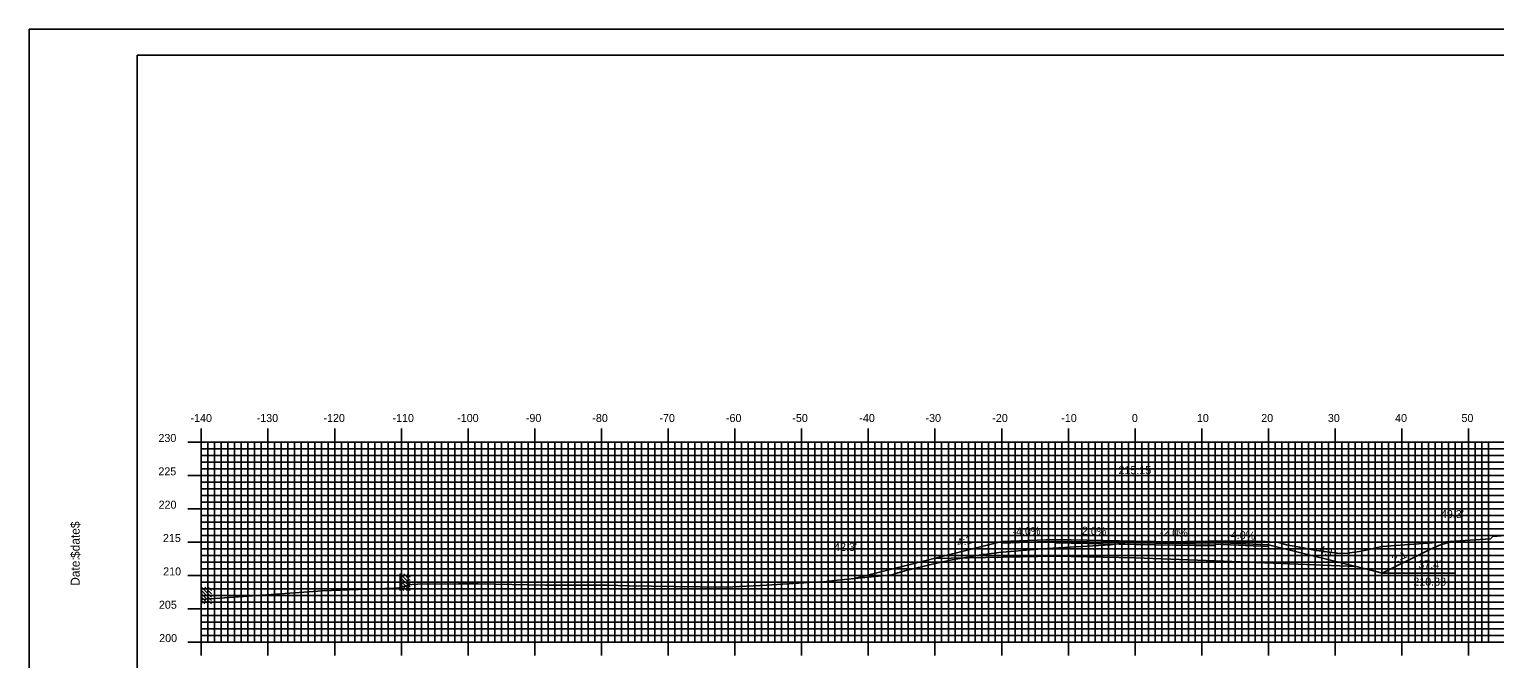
# Model space of a CAD drawing. Extents: x 851742 to 852085, y 364785 to 365005.
# Drawn here: x 851741.9 to 851961.6, y 364910.7 to 365005.1 of the extents above; entities that cross this region are included whole.
import ezdxf

# ---------------------------------------------------------------- set-up
doc = ezdxf.new("R2010")
doc.units = 0
for name, color, linetype in [('ANNOTATION', 7, 'Continuous'), ('BORDER', 7, 'Continuous'), ('D_Roadway_Centerline', 7, 'Continuous'), ('D_Roadway_Centerline_Text', 7, 'Continuous'), ('D_Roadway_Edge_Shoulder', 7, 'Continuous'), ('D_Roadway_Edge_TW', 7, 'Continuous'), ('D_Roadway_Pavement', 7, 'Continuous'), ('D_Roadway_SlopeLines', 7, 'Continuous'), ('D_Roadway_SubGrade', 7, 'Continuous'), ('D_Text_Standard', 7, 'Continuous'), ('H_V ANNOTATION', 7, 'Continuous'), ('M_Buildings_Rooftop', 7, 'Continuous'), ('MAJOR', 7, 'Continuous'), ('MINOR', 7, 'Continuous'), ('PDRAIN', 7, 'Continuous'), ('PLOT BOUNDARY', 7, 'Continuous'), ('S_Roadway_Centerline', 7, 'Continuous')]:
    doc.layers.add(name, color=color, linetype=linetype)

msp = doc.modelspace()

# ---------------------------------------------------------------- linework, layer by layer
at = {"layer": 'BORDER'}
msp.add_lwpolyline([(851758.1, 364791.23), (852078.1, 364791.23), (852078.1, 365001.23), (851758.1, 365001.23)], close=True, dxfattribs=at)
at = {"layer": 'D_Roadway_Centerline'}
msp.add_lwpolyline([(851877.53, 364925.76), (851887.7, 364928.3), (851895.7, 364928.62), (851907.7, 364928.38)], dxfattribs=at)
at = {"layer": 'D_Roadway_Edge_Shoulder'}
msp.add_lwpolyline([(851895.7, 364928.62), (851887.7, 364928.3), (851887.7, 364928.05), (851895.7, 364928.37)], close=True, dxfattribs=at)
msp.add_lwpolyline([(851927.7, 364927.82), (851927.7, 364927.57), (851919.7, 364927.89), (851907.7, 364928.13)], dxfattribs=at)
at = {"layer": 'D_Roadway_Edge_TW'}
msp.add_lwpolyline([(851907.7, 364928.13), (851895.7, 364928.37), (851895.7, 364928.62), (851907.7, 364928.38)], dxfattribs=at)
at = {"layer": 'D_Roadway_Pavement'}
msp.add_line((851939.61, 364924.61), (851940.75, 364924.56), dxfattribs=at)
for points in [[(851907.7, 364927.88), (851895.7, 364928.12), (851895.7, 364928.37), (851907.7, 364928.13)], [(851919.7, 364927.9), (851919.7, 364927.65), (851907.7, 364927.88)], [(851919.7, 364927.65), (851919.7, 364927.65)], [(851943.25, 364923.94), (851944.75, 364923.56), (851945.94, 364924.15)]]:
    msp.add_lwpolyline(points, dxfattribs=at)
at = {"layer": 'D_Roadway_SlopeLines'}
for points in [[(851887.7, 364928.3), (851865.39, 364922.72)], [(851944.75, 364923.56), (851951.99, 364927.18), (851953.24, 364927.73), (851954.49, 364928.13), (851955.74, 364928.37), (851956.99, 364928.47)]]:
    msp.add_lwpolyline(points, dxfattribs=at)
at = {"layer": 'D_Roadway_SubGrade'}
for points in [[(851939.61, 364924.61), (851919.7, 364925.4), (851907.7, 364925.88), (851895.7, 364926.12), (851877.53, 364925.76), (851887.7, 364928.3), (851887.7, 364928.05), (851895.7, 364928.37), (851907.7, 364928.13)], [(851907.7, 364928.38), (851919.71, 364928.14), (851927.7, 364927.82), (851943.25, 364923.94)]]:
    msp.add_lwpolyline(points, dxfattribs=at)
at = {"layer": 'M_Buildings_Rooftop'}
for p, q in [((851797.54, 364920.95), (851797.54, 364923.47)), ((851799.04, 364921.96), (851797.54, 364923.47)), ((851799.04, 364921.47), (851797.54, 364922.95)), ((851799.04, 364920.95), (851797.54, 364922.46)), ((851798.55, 364920.95), (851797.54, 364921.96)), ((851799.04, 364922.46), (851798.06, 364923.47)), ((851799.04, 364922.95), (851798.55, 364923.47)), ((851767.71, 364918.95), (851767.71, 364921.48)), ((851769.22, 364919.97), (851767.71, 364921.48)), ((851769.22, 364919.48), (851767.71, 364920.96)), ((851769.22, 364918.95), (851767.71, 364920.46)), ((851768.73, 364918.95), (851767.71, 364919.97)), ((851768.24, 364918.95), (851767.71, 364919.48)), ((851769.22, 364920.46), (851768.24, 364921.48)), ((851769.22, 364920.96), (851768.73, 364921.48)), ((851798.06, 364920.95), (851797.54, 364921.47))]:
    msp.add_line(p, q, dxfattribs=at)
at = {"layer": 'MAJOR'}
for p, q in [((851767.7, 364945.24), (851767.7, 364943.23)), ((851777.7, 364945.24), (851777.7, 364943.23)), ((851787.7, 364945.24), (851787.7, 364943.23)), ((851797.7, 364945.24), (851797.7, 364943.23)), ((851807.7, 364945.24), (851807.7, 364943.23)), ((851817.7, 364945.24), (851817.7, 364943.23)), ((851827.7, 364945.24), (851827.7, 364943.23)), ((851837.7, 364945.24), (851837.7, 364943.23)), ((851847.7, 364945.24), (851847.7, 364943.23)), ((851857.7, 364945.24), (851857.7, 364943.23)), ((851867.7, 364945.24), (851867.7, 364943.23)), ((851877.7, 364945.24), (851877.7, 364943.23)), ((851887.7, 364945.24), (851887.7, 364943.23)), ((851897.7, 364945.24), (851897.7, 364943.23)), ((851907.7, 364945.24), (851907.7, 364943.23)), ((851917.7, 364945.24), (851917.7, 364943.23)), ((851927.7, 364945.24), (851927.7, 364943.23)), ((851937.7, 364945.24), (851937.7, 364943.23)), ((851947.7, 364945.24), (851947.7, 364943.23)), ((851957.7, 364945.24), (851957.7, 364943.23)), ((851765.7, 364943.23), (851767.7, 364943.23)), ((851767.7, 364943.23), (852047.7, 364943.23)), ((851767.7, 364913.23), (851767.7, 364943.23)), ((851767.7, 364913.23), (851767.7, 364943.23)), ((851767.7, 364943.23), (852047.7, 364943.23)), ((851777.7, 364913.23), (851777.7, 364943.23)), ((851787.7, 364913.23), (851787.7, 364943.23)), ((851797.7, 364913.23), (851797.7, 364943.23)), ((851807.7, 364913.23), (851807.7, 364943.23)), ((851817.7, 364913.23), (851817.7, 364943.23)), ((851827.7, 364913.23), (851827.7, 364943.23)), ((851837.7, 364913.23), (851837.7, 364943.23)), ((851847.7, 364913.23), (851847.7, 364943.23)), ((851857.7, 364913.23), (851857.7, 364943.23)), ((851867.7, 364913.23), (851867.7, 364943.23)), ((851877.7, 364913.23), (851877.7, 364943.23)), ((851887.7, 364913.23), (851887.7, 364943.23)), ((851897.7, 364913.23), (851897.7, 364943.23)), ((851907.7, 364913.23), (851907.7, 364943.23)), ((851917.7, 364913.23), (851917.7, 364943.23)), ((851927.7, 364913.23), (851927.7, 364943.23)), ((851937.7, 364913.23), (851937.7, 364943.23)), ((851947.7, 364913.23), (851947.7, 364943.23)), ((851957.7, 364913.23), (851957.7, 364943.23)), ((851765.7, 364938.23), (851767.7, 364938.23)), ((851767.7, 364938.23), (852047.7, 364938.23)), ((851765.7, 364933.23), (851767.7, 364933.23)), ((851767.7, 364933.23), (852047.7, 364933.23)), ((851765.7, 364928.23), (851767.7, 364928.23)), ((851767.7, 364928.23), (852047.7, 364928.23)), ((851765.7, 364923.23), (851767.7, 364923.23)), ((851767.7, 364923.23), (852047.7, 364923.23)), ((851765.7, 364918.23), (851767.7, 364918.23)), ((851767.7, 364918.23), (852047.7, 364918.23)), ((851765.7, 364913.23), (851767.7, 364913.23)), ((851767.7, 364913.23), (852047.7, 364913.23)), ((851767.7, 364913.23), (852047.7, 364913.23)), ((851767.7, 364911.23), (851767.7, 364913.23)), ((851777.7, 364911.23), (851777.7, 364913.23)), ((851787.7, 364911.23), (851787.7, 364913.23)), ((851797.7, 364911.23), (851797.7, 364913.23)), ((851807.7, 364911.23), (851807.7, 364913.23)), ((851817.7, 364911.23), (851817.7, 364913.23)), ((851827.7, 364911.23), (851827.7, 364913.23)), ((851837.7, 364911.23), (851837.7, 364913.23)), ((851847.7, 364911.23), (851847.7, 364913.23)), ((851857.7, 364911.23), (851857.7, 364913.23)), ((851867.7, 364911.23), (851867.7, 364913.23)), ((851877.7, 364911.23), (851877.7, 364913.23)), ((851887.7, 364911.23), (851887.7, 364913.23)), ((851897.7, 364911.23), (851897.7, 364913.23)), ((851907.7, 364911.23), (851907.7, 364913.23)), ((851917.7, 364911.23), (851917.7, 364913.23)), ((851927.7, 364911.23), (851927.7, 364913.23)), ((851937.7, 364911.23), (851937.7, 364913.23)), ((851947.7, 364911.23), (851947.7, 364913.23)), ((851957.7, 364911.23), (851957.7, 364913.23))]:
    msp.add_line(p, q, dxfattribs=at)
at = {"layer": 'MINOR'}
for p, q in [((851767.7, 364942.23), (852047.7, 364942.23)), ((851767.7, 364942.23), (851769.71, 364942.23)), ((851768.7, 364913.23), (851768.7, 364943.23)), ((851769.7, 364913.23), (851769.7, 364943.23)), ((851770.7, 364913.23), (851770.7, 364943.23)), ((851771.7, 364913.23), (851771.7, 364943.23)), ((851772.7, 364913.23), (851772.7, 364943.23)), ((851773.7, 364913.23), (851773.7, 364943.23)), ((851774.7, 364913.23), (851774.7, 364943.23)), ((851775.7, 364913.23), (851775.7, 364943.23)), ((851776.7, 364913.23), (851776.7, 364943.23)), ((851778.7, 364913.23), (851778.7, 364943.23)), ((851779.7, 364913.23), (851779.7, 364943.23)), ((851780.7, 364913.23), (851780.7, 364943.23)), ((851781.7, 364913.23), (851781.7, 364943.23)), ((851782.7, 364913.23), (851782.7, 364943.23)), ((851783.7, 364913.23), (851783.7, 364943.23)), ((851784.7, 364913.23), (851784.7, 364943.23)), ((851785.7, 364913.23), (851785.7, 364943.23)), ((851786.7, 364913.23), (851786.7, 364943.23)), ((851788.7, 364913.23), (851788.7, 364943.23)), ((851789.7, 364913.23), (851789.7, 364943.23)), ((851790.7, 364913.23), (851790.7, 364943.23)), ((851791.7, 364913.23), (851791.7, 364943.23)), ((851792.7, 364913.23), (851792.7, 364943.23)), ((851793.7, 364913.23), (851793.7, 364943.23)), ((851794.7, 364913.23), (851794.7, 364943.23)), ((851795.7, 364913.23), (851795.7, 364943.23)), ((851796.7, 364913.23), (851796.7, 364943.23)), ((851798.7, 364913.23), (851798.7, 364943.23)), ((851799.7, 364913.23), (851799.7, 364943.23)), ((851800.7, 364913.23), (851800.7, 364943.23)), ((851801.7, 364913.23), (851801.7, 364943.23)), ((851802.7, 364913.23), (851802.7, 364943.23)), ((851803.7, 364913.23), (851803.7, 364943.23)), ((851804.7, 364913.23), (851804.7, 364943.23)), ((851805.7, 364913.23), (851805.7, 364943.23)), ((851806.7, 364913.23), (851806.7, 364943.23)), ((851808.7, 364913.23), (851808.7, 364943.23)), ((851809.7, 364913.23), (851809.7, 364943.23)), ((851810.7, 364913.23), (851810.7, 364943.23)), ((851811.7, 364913.23), (851811.7, 364943.23)), ((851812.7, 364913.23), (851812.7, 364943.23)), ((851813.7, 364913.23), (851813.7, 364943.23)), ((851814.7, 364913.23), (851814.7, 364943.23)), ((851815.7, 364913.23), (851815.7, 364943.23)), ((851816.7, 364913.23), (851816.7, 364943.23)), ((851818.7, 364913.23), (851818.7, 364943.23)), ((851819.7, 364913.23), (851819.7, 364943.23)), ((851820.7, 364913.23), (851820.7, 364943.23)), ((851821.7, 364913.23), (851821.7, 364943.23)), ((851822.7, 364913.23), (851822.7, 364943.23)), ((851823.7, 364913.23), (851823.7, 364943.23)), ((851824.7, 364913.23), (851824.7, 364943.23)), ((851825.7, 364913.23), (851825.7, 364943.23)), ((851826.7, 364913.23), (851826.7, 364943.23)), ((851828.7, 364913.23), (851828.7, 364943.23)), ((851829.7, 364913.23), (851829.7, 364943.23)), ((851830.7, 364913.23), (851830.7, 364943.23)), ((851831.7, 364913.23), (851831.7, 364943.23)), ((851832.7, 364913.23), (851832.7, 364943.23)), ((851833.7, 364913.23), (851833.7, 364943.23)), ((851834.7, 364913.23), (851834.7, 364943.23)), ((851835.7, 364913.23), (851835.7, 364943.23)), ((851836.7, 364913.23), (851836.7, 364943.23)), ((851838.7, 364913.23), (851838.7, 364943.23)), ((851839.7, 364913.23), (851839.7, 364943.23)), ((851840.7, 364913.23), (851840.7, 364943.23)), ((851841.7, 364913.23), (851841.7, 364943.23)), ((851842.7, 364913.23), (851842.7, 364943.23)), ((851843.7, 364913.23), (851843.7, 364943.23)), ((851844.7, 364913.23), (851844.7, 364943.23)), ((851845.7, 364913.23), (851845.7, 364943.23)), ((851846.7, 364913.23), (851846.7, 364943.23)), ((851848.7, 364913.23), (851848.7, 364943.23)), ((851849.7, 364913.23), (851849.7, 364943.23)), ((851850.7, 364913.23), (851850.7, 364943.23)), ((851851.7, 364913.23), (851851.7, 364943.23)), ((851852.7, 364913.23), (851852.7, 364943.23)), ((851853.7, 364913.23), (851853.7, 364943.23)), ((851854.7, 364913.23), (851854.7, 364943.23)), ((851855.7, 364913.23), (851855.7, 364943.23)), ((851856.7, 364913.23), (851856.7, 364943.23)), ((851858.7, 364913.23), (851858.7, 364943.23)), ((851859.7, 364913.23), (851859.7, 364943.23)), ((851860.7, 364913.23), (851860.7, 364943.23)), ((851861.7, 364913.23), (851861.7, 364943.23)), ((851862.7, 364913.23), (851862.7, 364943.23)), ((851863.7, 364913.23), (851863.7, 364943.23)), ((851864.7, 364913.23), (851864.7, 364943.23)), ((851865.7, 364913.23), (851865.7, 364943.23)), ((851866.7, 364913.23), (851866.7, 364943.23)), ((851868.7, 364913.23), (851868.7, 364943.23)), ((851869.7, 364913.23), (851869.7, 364943.23)), ((851870.7, 364913.23), (851870.7, 364943.23)), ((851871.7, 364913.23), (851871.7, 364943.23)), ((851872.7, 364913.23), (851872.7, 364943.23)), ((851873.7, 364913.23), (851873.7, 364943.23)), ((851874.7, 364913.23), (851874.7, 364943.23)), ((851875.7, 364913.23), (851875.7, 364943.23)), ((851876.7, 364913.23), (851876.7, 364943.23)), ((851878.7, 364913.23), (851878.7, 364943.23)), ((851879.7, 364913.23), (851879.7, 364943.23)), ((851880.7, 364913.23), (851880.7, 364943.23)), ((851881.7, 364913.23), (851881.7, 364943.23)), ((851882.7, 364913.23), (851882.7, 364943.23)), ((851883.7, 364913.23), (851883.7, 364943.23)), ((851884.7, 364913.23), (851884.7, 364943.23)), ((851885.7, 364913.23), (851885.7, 364943.23)), ((851886.7, 364913.23), (851886.7, 364943.23)), ((851888.7, 364913.23), (851888.7, 364943.23)), ((851889.7, 364913.23), (851889.7, 364943.23)), ((851890.7, 364913.23), (851890.7, 364943.23)), ((851891.7, 364913.23), (851891.7, 364943.23)), ((851892.7, 364913.23), (851892.7, 364943.23)), ((851893.7, 364913.23), (851893.7, 364943.23)), ((851894.7, 364913.23), (851894.7, 364943.23)), ((851895.7, 364913.23), (851895.7, 364943.23)), ((851896.7, 364913.23), (851896.7, 364943.23)), ((851898.7, 364913.23), (851898.7, 364943.23)), ((851899.7, 364913.23), (851899.7, 364943.23)), ((851900.7, 364913.23), (851900.7, 364943.23)), ((851901.7, 364913.23), (851901.7, 364943.23)), ((851902.7, 364913.23), (851902.7, 364943.23)), ((851903.7, 364913.23), (851903.7, 364943.23)), ((851904.7, 364913.23), (851904.7, 364943.23)), ((851905.7, 364913.23), (851905.7, 364943.23)), ((851906.7, 364913.23), (851906.7, 364943.23)), ((851908.7, 364913.23), (851908.7, 364943.23)), ((851909.7, 364913.23), (851909.7, 364943.23)), ((851910.7, 364913.23), (851910.7, 364943.23)), ((851911.7, 364913.23), (851911.7, 364943.23)), ((851912.7, 364913.23), (851912.7, 364943.23)), ((851913.7, 364913.23), (851913.7, 364943.23)), ((851914.7, 364913.23), (851914.7, 364943.23)), ((851915.7, 364913.23), (851915.7, 364943.23)), ((851916.7, 364913.23), (851916.7, 364943.23)), ((851918.7, 364913.23), (851918.7, 364943.23)), ((851919.7, 364913.23), (851919.7, 364943.23)), ((851920.7, 364913.23), (851920.7, 364943.23)), ((851921.7, 364913.23), (851921.7, 364943.23)), ((851922.7, 364913.23), (851922.7, 364943.23)), ((851923.7, 364913.23), (851923.7, 364943.23)), ((851924.7, 364913.23), (851924.7, 364943.23)), ((851925.7, 364913.23), (851925.7, 364943.23)), ((851926.7, 364913.23), (851926.7, 364943.23)), ((851928.7, 364913.23), (851928.7, 364943.23)), ((851929.7, 364913.23), (851929.7, 364943.23)), ((851930.7, 364913.23), (851930.7, 364943.23)), ((851931.7, 364913.23), (851931.7, 364943.23)), ((851932.7, 364913.23), (851932.7, 364943.23)), ((851933.7, 364913.23), (851933.7, 364943.23)), ((851934.7, 364913.23), (851934.7, 364943.23)), ((851935.7, 364913.23), (851935.7, 364943.23)), ((851936.7, 364913.23), (851936.7, 364943.23)), ((851938.7, 364913.23), (851938.7, 364943.23)), ((851939.7, 364913.23), (851939.7, 364943.23)), ((851940.7, 364913.23), (851940.7, 364943.23)), ((851941.7, 364913.23), (851941.7, 364943.23)), ((851942.7, 364913.23), (851942.7, 364943.23)), ((851943.7, 364913.23), (851943.7, 364943.23)), ((851944.7, 364913.23), (851944.7, 364943.23)), ((851945.7, 364913.23), (851945.7, 364943.23)), ((851946.7, 364913.23), (851946.7, 364943.23)), ((851948.7, 364913.23), (851948.7, 364943.23)), ((851949.7, 364913.23), (851949.7, 364943.23)), ((851950.7, 364913.23), (851950.7, 364943.23)), ((851951.7, 364913.23), (851951.7, 364943.23)), ((851952.7, 364913.23), (851952.7, 364943.23)), ((851953.7, 364913.23), (851953.7, 364943.23)), ((851954.7, 364913.23), (851954.7, 364943.23)), ((851955.7, 364913.23), (851955.7, 364943.23)), ((851956.7, 364913.23), (851956.7, 364943.23)), ((851958.7, 364913.23), (851958.7, 364943.23)), ((851959.7, 364913.23), (851959.7, 364943.23)), ((851960.7, 364913.23), (851960.7, 364943.23)), ((851767.7, 364941.23), (852047.7, 364941.23)), ((851767.7, 364941.23), (851769.71, 364941.23)), ((851767.7, 364940.23), (852047.7, 364940.23)), ((851767.7, 364940.23), (851769.71, 364940.23)), ((851767.7, 364939.23), (852047.7, 364939.23)), ((851767.7, 364939.23), (851769.71, 364939.23)), ((851767.7, 364937.23), (852047.7, 364937.23)), ((851767.7, 364937.23), (851769.71, 364937.23)), ((851767.7, 364936.23), (852047.7, 364936.23)), ((851767.7, 364936.23), (851769.71, 364936.23)), ((851767.7, 364935.23), (852047.7, 364935.23)), ((851767.7, 364935.23), (851769.71, 364935.23)), ((851767.7, 364934.23), (852047.7, 364934.23)), ((851767.7, 364934.23), (851769.71, 364934.23)), ((851767.7, 364932.23), (852047.7, 364932.23)), ((851767.7, 364932.23), (851769.71, 364932.23)), ((851767.7, 364931.23), (852047.7, 364931.23)), ((851767.7, 364931.23), (851769.71, 364931.23)), ((851767.7, 364930.23), (852047.7, 364930.23)), ((851767.7, 364930.23), (851769.71, 364930.23)), ((851767.7, 364929.23), (852047.7, 364929.23)), ((851767.7, 364929.23), (851769.71, 364929.23)), ((851767.7, 364927.23), (852047.7, 364927.23)), ((851767.7, 364927.23), (851769.71, 364927.23)), ((851767.7, 364926.23), (852047.7, 364926.23)), ((851767.7, 364926.23), (851769.71, 364926.23)), ((851767.7, 364925.23), (852047.7, 364925.23)), ((851767.7, 364925.23), (851769.71, 364925.23)), ((851767.7, 364924.23), (852047.7, 364924.23)), ((851767.7, 364924.23), (851769.71, 364924.23)), ((851767.7, 364922.23), (852047.7, 364922.23)), ((851767.7, 364922.23), (851769.71, 364922.23)), ((851767.7, 364921.23), (852047.7, 364921.23)), ((851767.7, 364921.23), (851769.71, 364921.23)), ((851767.7, 364920.23), (852047.7, 364920.23)), ((851767.7, 364920.23), (851769.71, 364920.23)), ((851767.7, 364919.23), (852047.7, 364919.23)), ((851767.7, 364919.23), (851769.71, 364919.23)), ((851767.7, 364917.23), (852047.7, 364917.23)), ((851767.7, 364917.23), (851769.71, 364917.23)), ((851767.7, 364916.23), (852047.7, 364916.23)), ((851767.7, 364916.23), (851769.71, 364916.23)), ((851767.7, 364915.23), (852047.7, 364915.23)), ((851767.7, 364915.23), (851769.71, 364915.23)), ((851767.7, 364914.23), (852047.7, 364914.23)), ((851767.7, 364914.23), (851769.71, 364914.23))]:
    msp.add_line(p, q, dxfattribs=at)
at = {"layer": 'PDRAIN'}
msp.add_line((851944.75, 364923.56), (851955.52, 364923.56), dxfattribs=at)
at = {"layer": 'PLOT BOUNDARY'}
msp.add_lwpolyline([(851741.92, 364785.11), (852081.92, 364785.11), (852081.92, 365005.11), (851741.92, 365005.11)], close=True, dxfattribs=at)
at = {"layer": 'S_Roadway_Centerline'}
msp.add_lwpolyline([(851767.7, 364919.64), (851785.87, 364920.92), (851796.56, 364921.33), (851797.36, 364921.37), (851798.29, 364921.6), (851798.9, 364921.8), (851799.32, 364921.89), (851800.12, 364921.92), (851803.73, 364921.94), (851803.75, 364921.94), (851803.8, 364921.93), (851806.27, 364921.98), (851809.2, 364921.97), (851819.32, 364921.75), (851828.48, 364921.76), (851831.85, 364921.68), (851838.53, 364921.58), (851846.41, 364921.47), (851852.45, 364921.79), (851860.45, 364922.24), (851860.57, 364922.22), (851860.57, 364922.22), (851863.08, 364922.49), (851863.08, 364922.49), (851871.29, 364923.32), (851871.96, 364923.57), (851873.16, 364923.93), (851877.71, 364924.99), (851880.26, 364925.56), (851882.59, 364925.98), (851884.85, 364926.35), (851885.46, 364926.42), (851887.28, 364926.67), (851893.12, 364927.16), (851894.58, 364927.28), (851894.58, 364927.25), (851902.19, 364927.69), (851904, 364927.83), (851906.89, 364928.2), (851911.83, 364928.25), (851918.68, 364928.38), (851919.9, 364928.43), (851925.67, 364928.37), (851927.24, 364928.33), (851928.72, 364928.19), (851929.27, 364928.15), (851930.39, 364927.83), (851932.95, 364927.36), (851934.8, 364926.94), (851934.89, 364926.95), (851937.64, 364926.6), (851937.73, 364926.57), (851938.03, 364926.55), (851939.77, 364926.53), (851939.91, 364926.63), (851941.34, 364926.82), (851944.73, 364927.56), (851955.66, 364928.38), (851960.96, 364928.72), (851961.31, 364929.04), (851974.57, 364930.11)], dxfattribs=at)

# ---------------------------------------------------------------- texts
at = {"layer": 'ANNOTATION'}
for s, rotation, p in [('-4.0%', 2.2906, (851889.34, 364929.17)), ('2.0%', 358.8542, (851899.71, 364929.34)), ('4:1', 14.0362, (851881.15, 364927.53)), ('-2.0%', 358.8542, (851911.39, 364929.11)), ('-4.0%', 357.7094, (851921.5, 364928.75)), ('4:1', 345.9638, (851935.16, 364926.58)), ('2:1', 26.5651, (851946.56, 364924.99))]:
    msp.add_text(s, height=1.2, rotation=rotation, dxfattribs=at).set_placement(p)
for s, p in [("37.4'", (851950.16, 364924.29)), ('210.33', (851949.41, 364921.69))]:
    msp.add_text(s, height=1.2, dxfattribs=at).set_placement(p)
at = {"layer": 'BORDER'}
for s, p in [('$date$', (851749.47, 364925.84)), ('Date:', (851749.47, 364921.67))]:
    msp.add_text(s, height=1.339, rotation=90, dxfattribs=at).set_placement(p)
at = {"layer": 'D_Roadway_Centerline'}
for s in ['C', 'L']:
    msp.add_text(s, height=0.0146, dxfattribs=at).set_placement((851907.7, 364928.38))
at = {"layer": 'D_Roadway_Centerline_Text'}
msp.add_text('215.15', height=1.2, dxfattribs=at).set_placement((851905.21, 364938.41))
at = {"layer": 'D_Text_Standard'}
for s, p in [("49.3'", (851953.55, 364931.83)), ("42.3'", (851862.57, 364926.9))]:
    msp.add_text(s, height=1.2, dxfattribs=at).set_placement(p)
at = {"layer": 'H_V ANNOTATION'}
for s, p in [('-140', (851766.09, 364946.23)), ('-130', (851776.01, 364946.23)), ('-120', (851786.02, 364946.23)), ('-110', (851796.37, 364946.23)), ('-100', (851806.07, 364946.23)), ('-90', (851816.36, 364946.23)), ('-80', (851826.33, 364946.23)), ('-70', (851836.39, 364946.23)), ('-60', (851846.36, 364946.23)), ('-50', (851856.31, 364946.23)), ('-40', (851866.36, 364946.23)), ('-30', (851876.28, 364946.23)), ('-20', (851886.29, 364946.23)), ('-10', (851896.63, 364946.23)), ('0', (851907.22, 364946.23)), ('10', (851916.96, 364946.23)), ('20', (851926.61, 364946.23)), ('30', (851936.6, 364946.23)), ('40', (851946.68, 364946.23)), ('50', (851956.63, 364946.23)), ('230', (851761.28, 364943.23)), ('225', (851761.27, 364938.23)), ('220', (851761.3, 364933.23)), ('215', (851761.95, 364928.23)), ('210', (851761.99, 364923.23)), ('205', (851761.35, 364918.23)), ('200', (851761.39, 364913.23))]:
    msp.add_text(s, height=1.2, dxfattribs=at).set_placement(p)
at = {"layer": 'MAJOR'}
msp.add_text('-', height=0.012, dxfattribs=at).set_placement((851767.7, 364913.23))
at = {"layer": 'S_Roadway_Centerline'}
for s, p in [('C', (851906.89, 364928.2)), ('L', (851906.88, 364928.19))]:
    msp.add_text(s, height=0.0146, dxfattribs=at).set_placement(p)

doc.saveas('drawing.dxf')
